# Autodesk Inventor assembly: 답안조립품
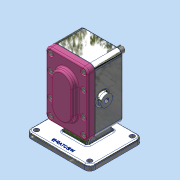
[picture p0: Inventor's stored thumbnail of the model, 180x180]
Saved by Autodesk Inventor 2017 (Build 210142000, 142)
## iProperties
Part Number: 답안조립품
Material: 일반
Document SubType Name: Assembly
Designer: MRC
Author: MRC
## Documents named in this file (11)
- C:\Users\MRC\Desktop\700407V1052\답안조립품.iam
- C:\Users\MRC\Desktop\700407V1052\본체.ipt
- C:\Users\MRC\Desktop\700407V1052\개스킷.ipt
- C:\Users\MRC\Desktop\700407V1052\메인축.ipt
- C:\Users\MRC\Desktop\700407V1052\베어링부시.ipt
- C:\Users\MRC\Desktop\700407V1052\볼트 M5.ipt
- C:\Users\MRC\Desktop\700407V1052\서브축.ipt
- C:\Users\MRC\Desktop\700407V1052\스퍼기어.ipt
- C:\Users\MRC\Desktop\700407V1052\오일 실 16 28 7.ipt
- C:\Users\MRC\Desktop\700407V1052\커버.ipt
- C:\Users\MRC\Desktop\700407V1052\키 6 x 6 x 18.ipt
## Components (1 placed, 1 different names)
1. 개스킷:1
